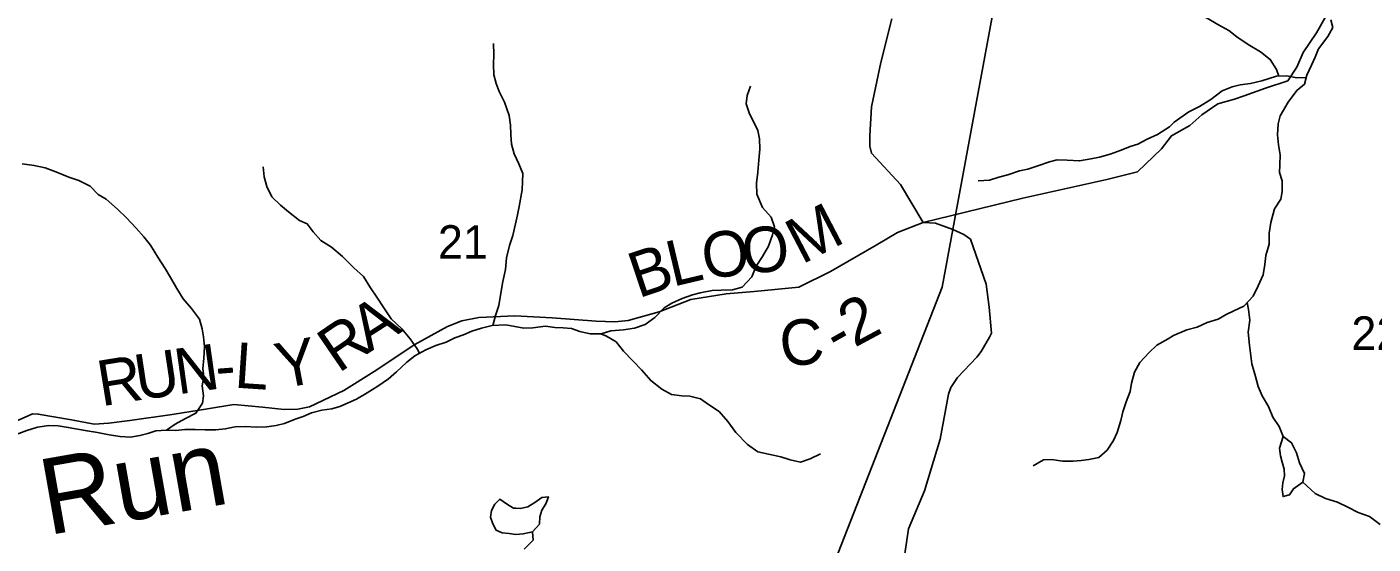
# Model space of a CAD drawing. Extents: x 1624196 to 2029251, y 146837 to 440034.
# Drawn here: x 1889620 to 1898481, y 258935 to 262342 of the extents above; entities that cross this region are included whole.
import ezdxf

# ---------------------------------------------------------------- set-up
doc = ezdxf.new("R2010")
doc.units = 0
for name, color, linetype in [('GM_X_County_Road', 7, 'Continuous'), ('GM_X_County_Road_Text', 7, 'Continuous'), ('GM_X_Minor_Lake', 7, 'Continuous'), ('GM_X_Minor_River', 7, 'Continuous'), ('GM_X_Minor_River_Text', 7, 'Continuous'), ('GM_X_Section', 7, 'Continuous'), ('GM_X_Section_Text', 7, 'Continuous')]:
    doc.layers.add(name, color=color, linetype=linetype)

msp = doc.modelspace()

# ---------------------------------------------------------------- linework, layer by layer
at = {"layer": 'GM_X_County_Road'}
for points in [[(1898588.7, 262736.5), (1898438, 262671.9), (1898347.4, 262610.6), (1898234.6, 262529.6), (1898108.4, 262302.5), (1898021.2, 262173.1), (1897978.2, 262077.4), (1897919.3, 261985.8), (1897772.9, 261939.1), (1897632.4, 261888.4), (1897568.2, 261867), (1897459.9, 261836), (1897353.1, 261762.9), (1897274.4, 261691.6), (1897153.8, 261624.6), (1897088.8, 261539.2), (1896929.6, 261387.6), (1896728.9, 261336.9), (1896175.1, 261214.2), (1895518.9, 261053.6)], [(1895518.9, 261053.6), (1895369.4, 261304.4), (1895179.9, 261509.7), (1895169.1, 261556.5), (1895169.1, 261624.7), (1895178.7, 261816.5), (1895239.7, 262107.3), (1895312.8, 262396.4)], [(1889443.4, 259697.3), (1889627.1, 259779.6), (1889656.1, 259792), (1889694.5, 259790.7), (1889912.3, 259752.4), (1890061.7, 259725.8), (1890158.3, 259731.8), (1890296.6, 259748.3), (1890575.2, 259789.4), (1890807.8, 259825), (1890982.2, 259855.2), (1891170.2, 259837.2), (1891314.1, 259821.7), (1891402.7, 259823), (1891480.4, 259839.9), (1891705.7, 259947.6), (1891905.2, 260071.6), (1892173.2, 260248.9), (1892388.7, 260368.7), (1892483, 260406.6), (1892595.5, 260428.6), (1892831.7, 260438.1), (1893077.8, 260425.5), (1893365.8, 260402.4), (1893488.8, 260398.3), (1893578, 260408.2), (1893780.7, 260464.1), (1893989.7, 260545.9), (1894222.3, 260583.5), (1894406.6, 260599.6), (1894701.2, 260626.5), (1894910.4, 260730.4), (1895210.4, 260903.3), (1895349.4, 260987.9), (1895518.9, 261053.6)], [(1895398.5, 258870.9), (1895422.9, 259035.6), (1895527.6, 259284.7), (1895631.3, 259625.9), (1895686.5, 259923.5), (1895701.1, 259967.3), (1895745.7, 260033), (1895873.2, 260165.8), (1895901.2, 260203.7), (1895955.8, 260296.9), (1895968.9, 260324.8), (1895953.5, 260494.7), (1895934.3, 260647.4), (1895831.3, 260942.8), (1895787.5, 260974.4), (1895713.9, 261008.1), (1895600.3, 261049.3), (1895518.9, 261053.6)]]:
    msp.add_lwpolyline(points, dxfattribs=at)
at = {"layer": 'GM_X_Minor_Lake'}
for points in [[(1897887.9, 259642.4), (1897865.6, 259566.4), (1897871.5, 259516.3), (1897883.3, 259474.2), (1897895.2, 259428.1), (1897897, 259384), (1897886.9, 259338), (1897882.7, 259294), (1897888.6, 259247.9), (1897930.6, 259259.8), (1897956.7, 259299.7), (1898019.3, 259342.7)], [(1898019.3, 259342.7), (1898029.1, 259399.5), (1897997.3, 259469.8), (1897977.5, 259535.9), (1897943.8, 259602.1), (1897887.9, 259642.4)], [(1892839, 259171.6), (1892822.5, 259172.4), (1892776.7, 259200.7), (1892733, 259231), (1892700.8, 259197.2), (1892678.5, 259155.3), (1892670.3, 259111.3), (1892686, 259067.2), (1892707.7, 259027), (1892747.5, 259008.7), (1892793.5, 259004.4), (1892837.4, 258998.2), (1892885.4, 259001.9), (1892947, 259015.1)], [(1892947, 259015.1), (1892993.7, 259065.2), (1892996, 259113.2), (1893008.3, 259157.2), (1893036.5, 259199.1), (1893052.8, 259247), (1893008.8, 259241.3), (1892962.6, 259209.6), (1892916.5, 259179.8), (1892868.5, 259170.1), (1892839, 259171.6)]]:
    msp.add_lwpolyline(points, dxfattribs=at)
at = {"layer": 'GM_X_Minor_River'}
for points in [[(1897860.1, 262017.7), (1897844.2, 262061.4), (1897804.4, 262127.6), (1897740.6, 262177.9), (1897658.7, 262226.3), (1897582.9, 262276.6), (1897531, 262318.9), (1897459.1, 262357.2), (1897389.3, 262399.5), (1897303.4, 262437.9), (1897235.6, 262476.2), (1897173.4, 262513.3)], [(1898203.3, 262388.3), (1898215.1, 262338.2), (1898182.9, 262278.3), (1898120.6, 262198.5), (1898100.4, 262142.5), (1898076.3, 262090.5), (1898044, 262024.5), (1898029.8, 261964.5), (1897979.7, 261922.7), (1897921.4, 261846.8), (1897869.1, 261756.9), (1897856.9, 261702.9), (1897852.7, 261630.8), (1897858.5, 261564.7), (1897870.2, 261498.6), (1897866, 261434.5), (1897865.8, 261382.5), (1897881.7, 261328.4), (1897881.4, 261258.3), (1897873.2, 261206.3), (1897831, 261144.3), (1897808.7, 261054.3), (1897796.5, 260982.3), (1897796.2, 260910.2), (1897774, 260836.2), (1897767.8, 260776.2), (1897757.5, 260708.1), (1897723.3, 260636.2), (1897691.1, 260568.2), (1897630.8, 260502.4), (1897564.7, 260470.6), (1897514.6, 260446.8), (1897460.5, 260416.9), (1897388.5, 260395.2), (1897322.4, 260363.4), (1897254.3, 260345.6), (1897167.3, 260308.9)], [(1892685.8, 260374.3), (1892703.8, 260440.1), (1892726.3, 260506), (1892738.9, 260588), (1892751.5, 260663.9), (1892770.2, 260743.9), (1892776.8, 260819.9), (1892795.4, 260901.9), (1892817.9, 260967.8), (1892836.5, 261045.7), (1892848.9, 261103.7), (1892859.4, 261159.6), (1892880.2, 261267.6), (1892882.6, 261321.7), (1892883.1, 261375.7), (1892857.6, 261440), (1892826.1, 261506.3), (1892808.6, 261568.5), (1892805.1, 261632.6), (1892803.6, 261694.7), (1892794.1, 261758.8), (1892762.9, 261847.2), (1892727.4, 261917.5), (1892707.9, 261969.8), (1892692.3, 262025.9), (1892690.9, 262094), (1892693.4, 262160.1), (1892690, 262232.2)], [(1898040.4, 262009.4), (1897978, 262006.8), (1897912, 262019), (1897844, 262017.3), (1897747.9, 261987.6), (1897673.8, 261969.9), (1897605.8, 261960.2), (1897553.8, 261946.3), (1897487.7, 261920.6), (1897413.5, 261864.8), (1897337.3, 261817), (1897267.2, 261783.3), (1897171.2, 261714.4)], [(1894390.6, 260695.1), (1894419.2, 260765), (1894461.6, 260828.7), (1894500.2, 260898.5), (1894526.7, 260972.4), (1894541.1, 261024.3), (1894519.6, 261088.5), (1894462.2, 261153.1), (1894424.9, 261239.5), (1894421.5, 261313.6), (1894430, 261385.6), (1894436.7, 261463.6), (1894443.2, 261537.6), (1894441.8, 261605.7), (1894430.2, 261659.9), (1894402.7, 261718.2), (1894375.1, 261768.4), (1894353.6, 261834.7), (1894360.1, 261890.7), (1894382.6, 261952.6)], [(1897171.2, 261714.4), (1897140.5, 261684.6), (1897062.1, 261633.2), (1896993.9, 261601.7), (1896931.7, 261570.1), (1896881.6, 261554.5), (1896821.5, 261530.9), (1896749.3, 261503.5), (1896679.2, 261484), (1896623.2, 261472.4), (1896549.1, 261459), (1896467.2, 261463.7), (1896401.3, 261466.2), (1896351.2, 261452.6), (1896275.1, 261427.1), (1896208.9, 261405.6), (1896152.9, 261394.1), (1896076.7, 261366.6), (1896016.7, 261353.1), (1895956.5, 261331.5), (1895880.6, 261328.1)], [(1890539.4, 259684.2), (1890595.6, 259723.8), (1890663.9, 259761.3), (1890732.1, 259796.8), (1890776.6, 259862.5), (1890783, 259912.5), (1890773.5, 259976.7), (1890784, 260038.7), (1890778.4, 260088.8), (1890784.9, 260158.8), (1890789.5, 260234.8), (1890782.1, 260301), (1890772.5, 260353.1), (1890755, 260417.3), (1890703.6, 260487.8), (1890648.1, 260550.3), (1890606.7, 260618.7), (1890565.3, 260691.1), (1890529.8, 260749.5), (1890482.4, 260825.9), (1890433.1, 260904.4), (1890389.5, 260958.8), (1890338, 261015.3), (1890274.6, 261083.8), (1890215.1, 261140.4), (1890141.7, 261207), (1890089.9, 261237.5), (1890036.4, 261291.9), (1889960.8, 261330.6), (1889895, 261353.1), (1889809.3, 261387.8), (1889739.6, 261414.4), (1889667.8, 261429), (1889587.9, 261439.6)], [(1892204.8, 260192.7), (1892188.5, 260221.9), (1892143, 260286.3), (1892087.6, 260352.8), (1892018.1, 260419.4), (1891968.7, 260491.9), (1891923.3, 260562.3), (1891881.8, 260622.7), (1891834.5, 260697.2), (1891771, 260755.8), (1891697.6, 260828.4), (1891624.1, 260891), (1891554.5, 260935.6), (1891505, 260992.1), (1891465.5, 261044.5), (1891413.7, 261066.9), (1891342.2, 261123.5), (1891288.6, 261168), (1891231, 261222.5), (1891199.6, 261290.8), (1891182.1, 261355), (1891174.6, 261419.2)], [(1889549.8, 259655.9), (1889620, 259683.4), (1889690.1, 259704.8), (1889764.2, 259716.3), (1889826.1, 259713.8), (1889892, 259703.3), (1889951.9, 259692.8), (1890015.7, 259680.3), (1890083.6, 259669.7), (1890161.4, 259655.1), (1890233.3, 259642.5), (1890301.2, 259638), (1890363.2, 259649.5), (1890415.3, 259663.1), (1890469.4, 259680.7), (1890539.4, 259684.2), (1890599.3, 259683.7), (1890659.3, 259689.2), (1890727.3, 259690.7), (1890793.2, 259688.2), (1890863.2, 259687.6), (1890925.2, 259693.2), (1890991.2, 259706.7), (1891059.2, 259710.1), (1891131.1, 259705.6), (1891199.1, 259707), (1891261.1, 259716.5), (1891315.2, 259728.1), (1891385.3, 259757.6), (1891437.5, 259775.2), (1891493.6, 259798.8), (1891561.7, 259816.3), (1891627.7, 259825.8), (1891679.8, 259841.4), (1891734, 259865), (1891790.1, 259888.6), (1891860.4, 259930.1), (1891928.7, 259975.6), (1891999, 260023.1), (1892053.3, 260068.8), (1892119.8, 260134.3), (1892174.1, 260175.9), (1892246.4, 260215.4), (1892310.5, 260242.9), (1892378.7, 260264.4), (1892436.8, 260294), (1892493, 260313.6), (1892549.1, 260337.2), (1892611.2, 260356.7), (1892683.3, 260374.2), (1892771.3, 260379.5), (1892831.2, 260369), (1892891, 260356.5), (1892951, 260360), (1893033, 260371.4), (1893094.9, 260360.9), (1893148.9, 260360.5), (1893204.8, 260354), (1893258.6, 260335.6), (1893328.4, 260319), (1893400.4, 260320.5), (1893464.5, 260340), (1893546.5, 260345.4), (1893618.5, 260356.8), (1893688.7, 260382.3), (1893753, 260427.8), (1893813.4, 260491.4), (1893865.6, 260523), (1893933.8, 260552.5), (1894002, 260576), (1894052, 260589.7), (1894130.1, 260605.1), (1894190.1, 260606.6), (1894264, 260610), (1894328.1, 260627.5), (1894390.6, 260695.1)], [(1897651.9, 260525.4), (1897660.8, 260480.2), (1897668.5, 260410.1), (1897658.2, 260330.1), (1897668, 260245.9), (1897673.8, 260191.9), (1897683.5, 260121.7), (1897707.3, 260039.5), (1897725, 259973.4), (1897750.8, 259911.2), (1897792.6, 259841), (1897820.3, 259770.8), (1897862.1, 259708.5), (1897887.9, 259642.4), (1897943.8, 259602.1), (1897977.5, 259535.9), (1897997.3, 259469.8), (1898029.1, 259399.5), (1898019.3, 259342.7), (1898098.6, 259267.1), (1898168.5, 259234.8), (1898246.4, 259210.5), (1898314.3, 259178.2), (1898382.2, 259141.9), (1898458.1, 259115.6), (1898528, 259063.2)], [(1893398.3, 260320.4), (1893434.2, 260304.2), (1893497.9, 260267.6), (1893547.4, 260205.2), (1893608.8, 260142.6), (1893664.3, 260082.1), (1893725.7, 260011.6), (1893799.2, 259954.9), (1893862.9, 259920.4), (1893930.8, 259911.9), (1893982.7, 259909.4), (1894054.5, 259890.9), (1894106.2, 259854.4), (1894175.8, 259807.8), (1894233.2, 259741.3), (1894286.6, 259668.8), (1894363.9, 259590.1), (1894431.5, 259543.5), (1894501.3, 259526.9), (1894583.1, 259510.3), (1894644.9, 259489.8), (1894710.8, 259475.2), (1894774.9, 259496.8), (1894843.1, 259528.2)], [(1897167.3, 260308.9), (1897131.5, 260287.1), (1897057.2, 260245.7), (1897006.8, 260198), (1896946.4, 260130.4), (1896909.9, 260066.6), (1896891.3, 259994.7), (1896882.9, 259940.7), (1896856.4, 259872.8), (1896833.9, 259806.9), (1896819.4, 259749), (1896796.8, 259669.1), (1896772.4, 259617.2), (1896730, 259553.5), (1896675.6, 259505.8), (1896609.6, 259492.3), (1896559.5, 259484.7), (1896507.5, 259481.1), (1896435.6, 259481.7), (1896365.7, 259492.3), (1896311.7, 259488.7), (1896243.5, 259449.2)], [(1892893.5, 258900.8), (1892952, 258960.4), (1892947, 259015.1)]]:
    msp.add_lwpolyline(points, dxfattribs=at)
at = {"layer": 'GM_X_Section'}
for points in [[(1889515.3, 263776.8), (1896140.5, 263314.2), (1895645.3, 260627.5), (1894640.5, 258058.6), (1889149.1, 258437.4)], [(1896140.5, 263314.2), (1898101.4, 263127.8), (1901479, 262738.8), (1901240.8, 257734.7), (1894640.5, 258058.6), (1895645.3, 260627.5)]]:
    msp.add_lwpolyline(points, close=True, dxfattribs=at)

# ---------------------------------------------------------------- texts
at = {"layer": 'GM_X_County_Road_Text'}
for s, rotation, p in [('M', 27.51113, (1894720.5, 260774)), ('O', 6.91988, (1894080, 260679.5)), ('O', 6.00348, (1894340.9, 260711.1)), ('B', 18.6028, (1893644, 260552.5)), ('L', 13.38346, (1893870.6, 260629.1)), ('A', 32.54984, (1891872.1, 260194.2)), ('2', 28.28753, (1895067.3, 260227.1)), ('R', 34.34107, (1891670.7, 260056.6)), ('C', 6.10788, (1894590.3, 260100.7)), ('-', 29.43236, (1894961.4, 260167.4)), ('N', 8.0111, (1890612.9, 259920.3)), ('L', 356.18308, (1890980.8, 259966)), ('Y', 10.72295, (1891287.5, 259956.1)), ('R', 9.28844, (1890110.4, 259841.5)), ('U', 8.56517, (1890352.6, 259881.1)), ('-', 4.4032, (1890869.3, 259956.6))]:
    msp.add_text(s, height=300, rotation=rotation, dxfattribs=at).set_placement(p)
at = {"layer": 'GM_X_Minor_River_Text'}
msp.add_text('Run', height=499.99, rotation=10.00035, dxfattribs=at).set_placement((1889757.4, 258992.2))
at = {"layer": 'GM_X_Section_Text'}
for s, p in [('21', (1892325.3, 260814.6)), ('22', (1898337.9, 260214))]:
    msp.add_text(s, height=221, rotation=0.00001, dxfattribs=at).set_placement(p)

doc.saveas('drawing.dxf')
